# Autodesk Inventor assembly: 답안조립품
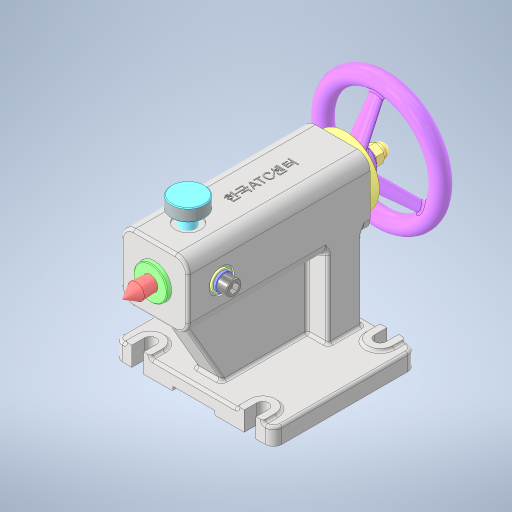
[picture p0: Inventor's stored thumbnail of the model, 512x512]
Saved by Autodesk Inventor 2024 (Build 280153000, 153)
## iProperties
Created: 2024-12
Part Number: 답안조립품
Document SubType Name: Assembly
Designer: user
Author: user
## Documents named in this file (15)
- C:\Users\user\Desktop\641204V1002\답안조립품.iam
- C:\Users\user\Desktop\641204V1002\본체\본체.ipt
- C:\Users\user\Desktop\641204V1002\나사축\나사축.ipt
- C:\Users\user\Desktop\641204V1002\부시\부시.ipt
- C:\Users\user\Desktop\641204V1002\센터\센터.ipt
- C:\Users\user\Desktop\641204V1002\스러스트 볼 베어링 51101\스러스트 볼 베어링 51101.ipt
- C:\Users\user\Desktop\641204V1002\스톱퍼\스톱퍼.ipt
- C:\Users\user\Desktop\641204V1002\스프링  와셔 M12\스프링  와셔 M12.ipt
- C:\Users\user\Desktop\641204V1002\슬리브\슬리브.ipt
- C:\Users\user\Desktop\641204V1002\육각 소켓 머리 볼트 M6x12\육각 소켓 머리 볼트 M6x12.ipt
- C:\Users\user\Desktop\641204V1002\육각 소켓 머리 볼트 M12x16\육각 소켓 머리 볼트 M12x16.ipt
- C:\Users\user\Desktop\641204V1002\캡너트 M12\캡너트 M12.ipt
- C:\Users\user\Desktop\641204V1002\평와셔 M12\평와셔 M12.ipt
- C:\Users\user\Desktop\641204V1002\평행키 4x4x14\평행키 4x4x14.ipt
- C:\Users\user\Desktop\641204V1002\핸들\핸들.ipt
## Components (1 placed, 1 different names)
1. 핸들:1
## Named parameters: d30_d23 = 0, d31_d26 = 0, d32_d23 = 0, d33_d26 = 0
